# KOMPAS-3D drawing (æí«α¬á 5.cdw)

Referenced files: ДМ 24-03.00.00 СБ.cdw
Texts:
  Редуктор цилинрический
  Алексей Такиулин Маратович
  Курсовое проектирование МиАС- 3-7  МГСУ (Московский Государственный Строительный Университет)  Каф.Дет.Маш
  МГСУ
  Noncommercial version
  Symbol type A
  степень
  точности
  Первая ступень-цилиндрическая передача
  Вторая ступень-цилиндрическая передача
  Номинальный вращающий момент на выходном валу Н*м
  Смазка
  передач
  подшипников
  окунанием
  консистентная
  марка масла
  объем масла
  пластическая смазка
  общее пере-
  даточное
  отношение
  ЦИАТИМ-202
  D-8х39х35 H7 js6 x8 F8 f8   ГОСТ1139-80
  Плоскость разреза покрыть герметиком при окончательной
  сборке.
  Необработаные поверхности красить внутри редуктора
  маслостойкой краской.
  Редуктор залить маслом И-100А
Dimensions and other numbers on the sheet: 102; 1; 31; 171; 5.51; 9; 144; 1.5; 35; 155; 8 16'; 4.42; 24.35; 550; 1.303; 40; 80; 404; 44; 22; 175,5; 421; 470; 285; 62; 30; 32; 25; 52; 20,5; 45; 115; 201; 2; 3; 4; 5; 6; 7; 8; 10; 11; 12; 13; 14; 15; 18; 28; 29; 19; 33; 20; 21; 23; 24; 26; 27; 34; 1:1; 25.06.06; 112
